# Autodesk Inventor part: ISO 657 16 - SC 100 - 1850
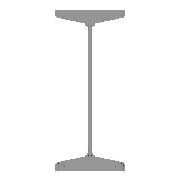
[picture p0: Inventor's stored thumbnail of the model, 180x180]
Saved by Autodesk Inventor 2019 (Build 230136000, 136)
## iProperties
_CCFamilyMember: 1
_CCFamilyDisplayName: ISO 657/16 - 1980 - Poutres en acier laminées à chaud - Partie 16: profilés en H (série métrique) - Cotes et propriétés de section
_FrameMemberDoc: Frame Member File
_Version: 15.0.0
_GetPNFromCC: 1
Created: 2018-07
Part Number: ISO 657 16 - SC 100 - 1850
Material: Acier, doux
Description: Poutres en acier laminées à chaud - Partie 16: profilés en H (série métrique) - Cotes et propriétés de section
Document SubType Name: Modeling
Standard: ISO
Designer: Fabian Perrée
Standard Revision: First edition 1980-02-15
Standards Organization: ISO
Language: fr-FR
Size Designation: SC 100
Categories: <MemberInstance><Categories><Category DisplayName="Profilés" InternalName="089c4875-fa83-4c05-b084-43b9cc11f5ed" Mnemonic="GRDR"><CategoryParameter DisplayName=
Stock Number: SC 100
Density: 7.85 g/cm^3
Appearance: Semi-poli
Mass: 33560.6 g
Surface Area: 9272.62 cm^2
Volume: 4275.24 cm^3
IsCustomPart: 1
G_W: 100,000 mm
G_H: 100,000 mm
G_L: 1850,000 mm
+3996474A-F15E-4C0C-B350-EF0BE35A7832+DETAILDECOUPE6: Angle de coupe 90,00 deg
+49FB2D49-B789-45CC-8DEB-3E9423125D72+DETAILDECOUPE7: Angle de coupe 90,00 deg
Author: Fabian Perrée
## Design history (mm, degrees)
node "Plan de départ"
node "Plan de fin"
sketch "Esquisse"
  geometry: L1 (-3, 0)-(-3, -26.266); L2 (-13.33, -38.149)-(-44.835, -42.577); L3 (-50, -48.518)-(-50, -50); L4 (-50, -50)-(0, -50); L5 (-26.5, -50)-(-26.5, -40); L6 (-61.333, 0)-(81.777, 0); L7 (0, 0)-(0, -50); L8 (0, -60)-(0, 80); L9 (3, 0)-(3, -26.266); L10 (13.33, -38.149)-(44.835, -42.577); L11 (50, -48.518)-(50, -50); L12 (50, -50)-(0, -50); L13 (-3, 0)-(0, 0); L14 (-3, 0)-(-3, 26.266); L15 (-13.33, 38.149)-(-44.835, 42.577); L16 (-50, 48.518)-(-50, 50); L17 (-50, 50)-(0, 50); L18 (50, 48.518)-(50, 50); L19 (13.33, 38.149)-(44.835, 42.577); L20 (3, 0)-(3, 26.266); L21 (50, 50)-(0, 50); L22 (0, 108)-(0, -88) reference; L23 (-89.955, 0)-(110.399, 0) reference; A1 r 6 centre (-44, 48.518) between (-50, 48.518) and (-44.835, 42.577); A2 r 6 centre (44, 48.518) between (44.835, 42.577) and (50, 48.518); A3 r 6 centre (44, -48.518) between (50, -48.518) and (44.835, -42.577); A4 r 6 centre (-44, -48.518) between (-44.835, -42.577) and (-50, -48.518); A5 r 12 centre (-15, 26.266) between (-3, 26.266) and (-13.33, 38.149); A6 r 12 centre (15, 26.266) between (13.33, 38.149) and (3, 26.266); A7 r 12 centre (15, -26.266) between (3, -26.266) and (13.33, -38.149); A8 r 12 centre (-15, -26.266) between (-13.33, -38.149) and (-3, -26.266); 14 further points
  constraints: 42 end point, 24 point on line, 17 symmetric about line, 16 point on circle, 16 tangent, 8 centre point, 6 equal radius, 4 collinear, 2 perpendicular, 12 other
  dimensions: "d1" = 10 vertical distance of L3.end L5.end (= G_T1); "d2" = 23.5 distance between parallel lines of L5 L3 (= -0.25 x G_T + 0.25 x G_W); "d3" = 3 distance between parallel lines of L1 L7 (= 0.5 x G_T); "d4" = 50 distance between parallel lines of L7 L3 (= 0.5 x G_W); "d9" = 50 distance from line of L1.start L4 (= 0.5 x G_H); "d14" = 98 deg angle of L2 L1 (= G_NG); "d15" = 6 radius of A1 (= G_ER); "d16" = 12 radius of A5 (= G_IR)
extrude "Corps" new body sketch "Esquisse" stored distance "d5" = 1850 (= G_L); taper "d6" = 0 deg
node "Driven Length"
  sketch "Sketch3"
    geometry: L1 (0, 0)-(10, 0) reference
    constraints: 2 end point, 1 horizontal
  workplane "Work Plane3"
  sketch "Sketch4"
    geometry: L1 (-2, -50)-(12, -50) reference; L2 (-2, 1800)-(12, 1800) reference
    dimensions: "d20" = 1850 distance between parallel lines of L1 L2 (derived)
node "Plan de construction17"
feature "Scission5"
node "Plan de construction18"
feature "Scission6"
body "Solid1"
other parameters: "G_W" = 100 (= G_H) [user parameter; used in 2 equation terms], "G_H" = 100 [user parameter; used in 2 equation terms], "G_T" = 6 [user parameter; used in 2 equation terms], "G_T1" = 10 [user parameter; used in 1 equation term], "G_L" = 1850 (= d20) [user parameter; used in 1 equation term], "G_ER" = 6 [user parameter; used in 1 equation term], "G_IR" = 12 [user parameter; used in 1 equation term], "G_NG" = 98 deg [user parameter; used in 1 equation term], "d19" = 90 deg
